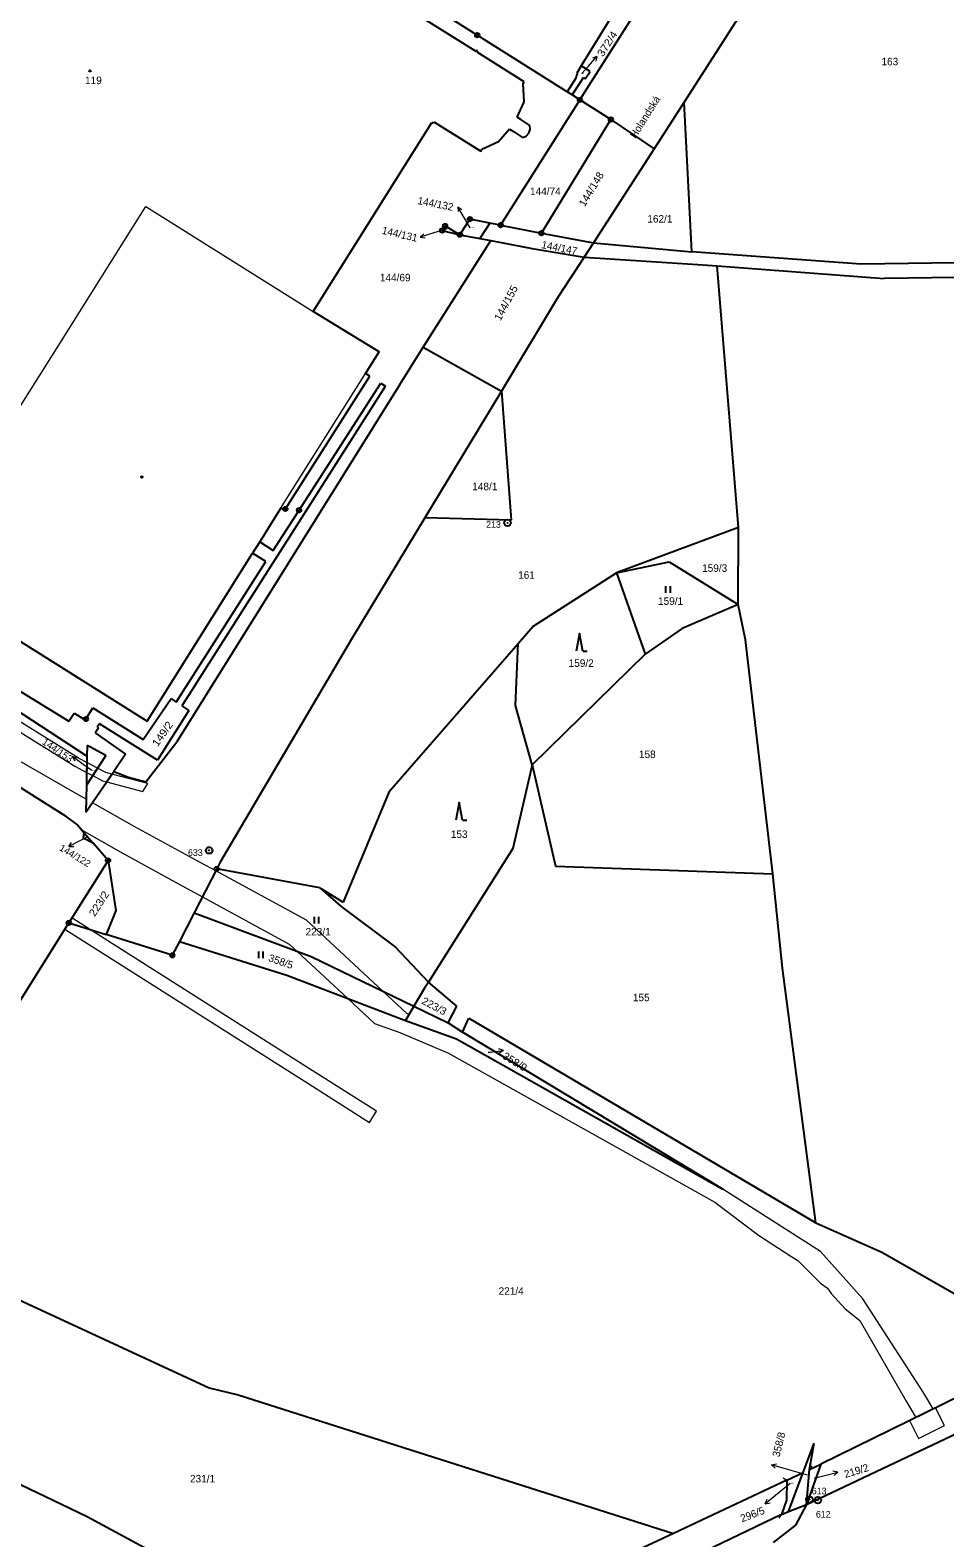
# Model space of a CAD drawing. Extents: x -645290 to -643454, y -1064771 to -1062356.
# Drawn here: x -644073.2 to -643865.7, y -1063369.7 to -1063027.7 of the extents above; entities that cross this region are included whole.
import ezdxf
from ezdxf.enums import TextEntityAlignment as Align

# ---------------------------------------------------------------- set-up
doc = ezdxf.new("R2010")
doc.units = 0
doc.header["$LTSCALE"] = 0.68
for name, color, linetype, lineweight in [('1', 7, 'Continuous', 25), ('13', 7, 'Continuous', 13), ('3', 7, 'Continuous', 25), ('4', 7, 'Continuous', 13), ('5', 7, 'Continuous', 25), ('7', 7, 'Continuous', 13), ('8', 7, 'Continuous', 25)]:
    doc.layers.add(name, color=color, linetype=linetype, lineweight=lineweight)
doc.layers.add('2', color=7, linetype='Continuous')

msp = doc.modelspace()

# ---------------------------------------------------------------- linework, layer by layer
at = {"layer": '1'}
for p, q in [((-643972.05, -1063032.56), (-644071.08, -1062970.39)), ((-643948.47, -1063043.52), (-643911.32, -1062984.88)), ((-643886.01, -1062983.52), (-643924.81, -1063044)), ((-643919.63, -1062989.21), (-643948.16, -1063035.76)), ((-643971.78, -1063028.84), (-644020.09, -1062998.39)), ((-643951.4, -1063041.68), (-643971.78, -1063028.84)), ((-643971.91, -1063032.34), (-643972.05, -1063032.56)), ((-643971.86, -1063032.26), (-643971.91, -1063032.34)), ((-643971.61, -1063032.42), (-643971.86, -1063032.26)), ((-643971.8, -1063032.72), (-643971.61, -1063032.42)), ((-643961.09, -1063039.44), (-643971.8, -1063032.72)), ((-643948.16, -1063035.76), (-643949.21, -1063037.48)), ((-643946.13, -1063037.05), (-643948.16, -1063035.76)), ((-643961.33, -1063039.82), (-643961.09, -1063039.44)), ((-643961.09, -1063043.97), (-643961.33, -1063039.82)), ((-643949.39, -1063038.58), (-643951.4, -1063041.68)), ((-643950.24, -1063042.41), (-643948.23, -1063039.28)), ((-643949.22, -1063037.96), (-643949.39, -1063038.58)), ((-643949.11, -1063037.54), (-643949.22, -1063037.96)), ((-643949.21, -1063037.48), (-643949.11, -1063037.54)), ((-643948.23, -1063039.28), (-643947.85, -1063038.67)), ((-643947.85, -1063038.67), (-643947.72, -1063038.46)), ((-643947.72, -1063038.46), (-643947.26, -1063038.77)), ((-643947.26, -1063038.77), (-643946.13, -1063037.05)), ((-643948.47, -1063043.52), (-643966.47, -1063071.93)), ((-643950.24, -1063042.41), (-643951.4, -1063041.68)), ((-643948.47, -1063043.52), (-643950.24, -1063042.41)), ((-643941.45, -1063047.96), (-643948.47, -1063043.52)), ((-643962.73, -1063047.41), (-643961.09, -1063043.97)), ((-643924.81, -1063044), (-643931.65, -1063054.65)), ((-643923.12, -1063077.97), (-643924.81, -1063044)), ((-644009.01, -1063091.53), (-643982.06, -1063048.68)), ((-643982.06, -1063048.68), (-643981.78, -1063048.77)), ((-643981.78, -1063048.77), (-643981.64, -1063048.5)), ((-643981.64, -1063048.5), (-643972.77, -1063054.04)), ((-643964.46, -1063050.17), (-643966.94, -1063053.05)), ((-643964.46, -1063050.17), (-643963.58, -1063050.72)), ((-643961.86, -1063047.99), (-643962.73, -1063047.41)), ((-643959.85, -1063049.36), (-643961.86, -1063047.99)), ((-643960.07, -1063051.08), (-643959.78, -1063050.25)), ((-643959.78, -1063050.25), (-643959.85, -1063049.36)), ((-643957.21, -1063073.75), (-643941.45, -1063047.96)), ((-643941.45, -1063047.96), (-643931.65, -1063054.65)), ((-643966.94, -1063053.05), (-643970.71, -1063054.8)), ((-643963.58, -1063050.72), (-643961.51, -1063052.03)), ((-643961.51, -1063052.03), (-643960.67, -1063051.72)), ((-643960.67, -1063051.72), (-643960.07, -1063051.08)), ((-643972.77, -1063054.04), (-643970.95, -1063055.18)), ((-643970.95, -1063055.18), (-643970.71, -1063054.8)), ((-643931.65, -1063054.65), (-643945.43, -1063075.94)), ((-643975.72, -1063074.1), (-643973.43, -1063070.56)), ((-643968.91, -1063071.45), (-643973.43, -1063070.56)), ((-643979.72, -1063073.14), (-643979.06, -1063072.12)), ((-643979.72, -1063073.14), (-643975.72, -1063074.1)), ((-643979.06, -1063072.12), (-643975.72, -1063074.1)), ((-643975.72, -1063074.1), (-643971.17, -1063074.97)), ((-643968.91, -1063071.45), (-643971.17, -1063074.97)), ((-643966.47, -1063071.93), (-643968.91, -1063071.45)), ((-643966.47, -1063071.93), (-643957.21, -1063073.75)), ((-643957.21, -1063073.75), (-643945.43, -1063075.94)), ((-643984.01, -1063099.62), (-643968.69, -1063075.44)), ((-643971.17, -1063074.97), (-643968.69, -1063075.44)), ((-643968.69, -1063075.44), (-643959.33, -1063077.22)), ((-643959.33, -1063077.22), (-643947.54, -1063079.19)), ((-643945.43, -1063075.94), (-643947.54, -1063079.19)), ((-643945.43, -1063075.94), (-643923.12, -1063077.97)), ((-643947.54, -1063079.19), (-643953.38, -1063088.21)), ((-643947.54, -1063079.19), (-643921.76, -1063080.86)), ((-643884.68, -1063080.78), (-643923.12, -1063077.97)), ((-643921.76, -1063080.86), (-643917.3, -1063081.19)), ((-643912.5, -1063140.52), (-643917.3, -1063081.19)), ((-643917.3, -1063081.19), (-643879.42, -1063084.02)), ((-643837.07, -1063080.08), (-643884.68, -1063080.78)), ((-643833.92, -1063083.46), (-643879.42, -1063084.02)), ((-643953.38, -1063088.21), (-643966.3, -1063109.61)), ((-643989.36, -1063108.06), (-643984.01, -1063099.62)), ((-643984.01, -1063099.62), (-643966.3, -1063109.61)), ((-643989.36, -1063108.06), (-644039.93, -1063189.16)), ((-644015.31, -1063136.3), (-643996.12, -1063106.19)), ((-644012.2, -1063136.58), (-643993.65, -1063107.74)), ((-644010.59, -1063136.73), (-643992.55, -1063108.43)), ((-643996.12, -1063106.19), (-643997.14, -1063105.55)), ((-643993.65, -1063107.74), (-643992.55, -1063108.43)), ((-643966.3, -1063109.61), (-643983.63, -1063138.3)), ((-643966.3, -1063109.61), (-643964.11, -1063138.86)), ((-644035.79, -1063176.25), (-644010.59, -1063136.73)), ((-644016.38, -1063136.2), (-644021.12, -1063143.76)), ((-644018.07, -1063145.71), (-644012.2, -1063136.58)), ((-644015.31, -1063136.3), (-644016.38, -1063136.2)), ((-643983.63, -1063138.3), (-644000.27, -1063165.84)), ((-643964.11, -1063138.86), (-643983.63, -1063138.3)), ((-643912.5, -1063140.52), (-643940.21, -1063150.77)), ((-643912.54, -1063157.95), (-643912.5, -1063140.52)), ((-644021.12, -1063143.76), (-644022.73, -1063146.32)), ((-644021.12, -1063143.76), (-644018.07, -1063145.71)), ((-644046.66, -1063184.45), (-644022.73, -1063146.32)), ((-644040.05, -1063180.11), (-644019.72, -1063148.25)), ((-644019.72, -1063148.25), (-644022.73, -1063146.32)), ((-643940.21, -1063150.77), (-643928.21, -1063148.29)), ((-643928.21, -1063148.29), (-643912.54, -1063157.95)), ((-644100.11, -1063150.87), (-644046.66, -1063184.45)), ((-643959.16, -1063163.01), (-643940.21, -1063150.77)), ((-643940.21, -1063150.77), (-643933.67, -1063169.22)), ((-644060.32, -1063192.37), (-644113.26, -1063157.87)), ((-644105.82, -1063159.04), (-644064.47, -1063184.41)), ((-643912.54, -1063157.95), (-643925.3, -1063163.46)), ((-643910.9, -1063165.99), (-643912.54, -1063157.95)), ((-643962.49, -1063166.82), (-643959.16, -1063163.01)), ((-644000.27, -1063165.84), (-644030.1, -1063216.46)), ((-643925.3, -1063163.46), (-643933.67, -1063169.22)), ((-643904.73, -1063219.08), (-643910.9, -1063165.99)), ((-643991.77, -1063200.37), (-643962.49, -1063166.82)), ((-643963.07, -1063180.87), (-643962.49, -1063166.82)), ((-643933.67, -1063169.22), (-643959.3, -1063194.35)), ((-644120.82, -1063170.91), (-644065.09, -1063205.97)), ((-644035.79, -1063176.25), (-644038.78, -1063180.95)), ((-644047.54, -1063188.64), (-644041.24, -1063179.32)), ((-644041.24, -1063179.32), (-644040.05, -1063180.11)), ((-644064.47, -1063184.41), (-644063.23, -1063182.62)), ((-644063.23, -1063182.62), (-644060.69, -1063184.18)), ((-644060.56, -1063183.97), (-644058.98, -1063181.46)), ((-644058.98, -1063181.46), (-644047.54, -1063188.64)), ((-644037.2, -1063182), (-644044.35, -1063193.29)), ((-644038.78, -1063180.95), (-644037.2, -1063182)), ((-643959.3, -1063194.35), (-643963.07, -1063180.87)), ((-644060.69, -1063184.18), (-644060.56, -1063183.97)), ((-644057.71, -1063186.02), (-644058.43, -1063187.12)), ((-644058.43, -1063187.12), (-644051.58, -1063191.93)), ((-644057.51, -1063185.02), (-644058.02, -1063185.83)), ((-644058.02, -1063185.83), (-644057.71, -1063186.02)), ((-644044.35, -1063193.29), (-644057.51, -1063185.02)), ((-644060.28, -1063189.93), (-644060.32, -1063192.37)), ((-644059.49, -1063190.36), (-644060.28, -1063189.93)), ((-644058.04, -1063191.16), (-644059.49, -1063190.36)), ((-644046.99, -1063198.23), (-644039.93, -1063189.16)), ((-644056.03, -1063192.27), (-644060.44, -1063198.94)), ((-644060.32, -1063192.37), (-644060.44, -1063198.94)), ((-644056.03, -1063192.27), (-644058.04, -1063191.16)), ((-644051.58, -1063191.93), (-644054.25, -1063195.85)), ((-644060.55, -1063205.1), (-644054.25, -1063195.85)), ((-644054.25, -1063195.85), (-644050.87, -1063197.15)), ((-644050.87, -1063197.15), (-644046.99, -1063198.23)), ((-643959.3, -1063194.35), (-643963.72, -1063213.32)), ((-643959.3, -1063194.35), (-643954.05, -1063217.36)), ((-644060.44, -1063198.94), (-644060.55, -1063205.1)), ((-643991.77, -1063200.37), (-644002.22, -1063225.49)), ((-644062.5, -1063207.96), (-644065.09, -1063205.97)), ((-644062.5, -1063207.96), (-644061.02, -1063209.68)), ((-644061.02, -1063209.68), (-644061.15, -1063211.01)), ((-644058.9, -1063212.14), (-644061.15, -1063211.01)), ((-644061.02, -1063209.68), (-644058.9, -1063212.14)), ((-644055.54, -1063216.03), (-644058.9, -1063212.14)), ((-643963.72, -1063213.32), (-643982.84, -1063243.64)), ((-644055.54, -1063216.03), (-644064.43, -1063230.22)), ((-644055.54, -1063216.03), (-644055.3, -1063217.57)), ((-644055.3, -1063217.57), (-644053.77, -1063227.42)), ((-644030.87, -1063217.96), (-644036.02, -1063227.96)), ((-644030.1, -1063216.46), (-644030.87, -1063217.96)), ((-644007.47, -1063222.27), (-644030.87, -1063217.96)), ((-643954.05, -1063217.36), (-643904.73, -1063219.08)), ((-643902.48, -1063240.48), (-643904.73, -1063219.08)), ((-644007.47, -1063222.27), (-644002.22, -1063225.49)), ((-644007.47, -1063222.27), (-644002.63, -1063226.47)), ((-644053.77, -1063227.42), (-644056, -1063232.86)), ((-644036.02, -1063227.96), (-644039.36, -1063234.45)), ((-644036.02, -1063227.96), (-644009.43, -1063237.85)), ((-644002.63, -1063226.47), (-643990.35, -1063235.73)), ((-644108.45, -1063300.52), (-644064.43, -1063230.22)), ((-644064.43, -1063230.22), (-644056, -1063232.86)), ((-644040.97, -1063237.56), (-644056, -1063232.86)), ((-644039.36, -1063234.45), (-644040.97, -1063237.56)), ((-644039.36, -1063234.45), (-644014.97, -1063242.04)), ((-644009.43, -1063237.85), (-643986.15, -1063249.13)), ((-643982.84, -1063243.64), (-643990.35, -1063235.73)), ((-643894.95, -1063298.27), (-643902.48, -1063240.48)), ((-644014.97, -1063242.04), (-643988.07, -1063252.36)), ((-643983.72, -1063245.03), (-643986.15, -1063249.13)), ((-643982.84, -1063243.64), (-643983.72, -1063245.03)), ((-643976.39, -1063249.11), (-643982.84, -1063243.64)), ((-643986.15, -1063249.13), (-643988.07, -1063252.36)), ((-643986.15, -1063249.13), (-643978.34, -1063252.91)), ((-643978.34, -1063252.91), (-643976.39, -1063249.11)), ((-643975.08, -1063255.03), (-643973.71, -1063251.82)), ((-643973.71, -1063251.82), (-643894.95, -1063298.27)), ((-643988.07, -1063252.36), (-643976.48, -1063256.51)), ((-643978.34, -1063252.91), (-643975.08, -1063255.03)), ((-643916.03, -1063290.57), (-643975.08, -1063255.03)), ((-643976.48, -1063256.51), (-643916.03, -1063290.57)), ((-643894.95, -1063298.27), (-643880.01, -1063304.89)), ((-644108.45, -1063300.52), (-644032.62, -1063335.66)), ((-643880.01, -1063304.89), (-643861.29, -1063315.59)), ((-644128.32, -1063332.26), (-644060.42, -1063364.75)), ((-644032.62, -1063335.66), (-644026.05, -1063337.25)), ((-644026.05, -1063337.25), (-643927.27, -1063368.68)), ((-643857.36, -1063335.06), (-643893.79, -1063352.95)), ((-643897.06, -1063362.17), (-643858.41, -1063343.81)), ((-643897.81, -1063354.89), (-643895.32, -1063348.19)), ((-643896.36, -1063354.21), (-643895.32, -1063348.19)), ((-643893.79, -1063352.95), (-643897.06, -1063362.17)), ((-643897.06, -1063362.17), (-643896.36, -1063354.21)), ((-643896.36, -1063354.21), (-643893.79, -1063352.95)), ((-643901.5, -1063356.61), (-643927.27, -1063368.68)), ((-643901.5, -1063356.61), (-643901.57, -1063361.14)), ((-643901.5, -1063356.61), (-643897.81, -1063354.89)), ((-643901.12, -1063363.76), (-643897.81, -1063354.89)), ((-643901.57, -1063361.14), (-643902.76, -1063364.4)), ((-644060.42, -1063364.75), (-644036.09, -1063377.9)), ((-643902.76, -1063364.4), (-643990.03, -1063406.29)), ((-643902.76, -1063364.4), (-643901.12, -1063363.76)), ((-643901.12, -1063363.76), (-643897.06, -1063362.17)), ((-643897.06, -1063362.17), (-643899.58, -1063366.85)), ((-643899.58, -1063366.85), (-643904.6, -1063370.72)), ((-643927.27, -1063368.68), (-643987.39, -1063396.85))]:
    msp.add_line(p, q, dxfattribs=at)
msp.add_lwpolyline([(-643997.14, -1063105.55), (-643994.05, -1063100.64), (-644009.01, -1063091.53)], dxfattribs=at)
at = {"layer": '13'}
for points in [[(-644175.47, -1063119.76), (-644177.34, -1063118.44), (-644175.73, -1063115.62), (-644177.14, -1063114.69), (-644177.4, -1063114.52), (-644180.02, -1063119.08), (-644176.52, -1063121.53), (-644166.59, -1063128.45), (-644146.52, -1063141.67), (-644115.44, -1063161.49), (-644083.43, -1063182.03), (-644063.09, -1063194.64), (-644060.39, -1063196.06), (-644060.35, -1063193.82), (-644062.09, -1063192.9), (-644082.37, -1063180.33), (-644114.36, -1063159.81), (-644145.44, -1063139.99), (-644165.45, -1063126.81)], [(-644059.01, -1063196.79), (-644056.77, -1063197.98), (-644055.86, -1063198.22), (-644054.66, -1063196.45), (-644056.07, -1063196.08), (-644057.91, -1063195.11), (-644060.35, -1063193.82), (-644060.39, -1063196.06)], [(-644055.86, -1063198.22), (-644047.65, -1063200.37), (-644046.53, -1063198.6), (-644054.66, -1063196.45)], [(-643996.24, -1063275.47), (-643994.63, -1063272.94), (-644010.67, -1063262.76), (-644059.48, -1063231.77), (-644063.72, -1063229.08), (-644064.43, -1063230.22), (-644065.31, -1063231.62), (-644010.85, -1063266.19)], [(-643873.7, -1063343.09), (-643871.64, -1063347.17), (-643865.75, -1063344.2), (-643867.78, -1063340.18), (-643868.35, -1063340.46), (-643872.3, -1063342.4)]]:
    msp.add_lwpolyline(points, close=True, dxfattribs=at)
msp.add_lwpolyline([(-644122.95, -1063169.57), (-644065.09, -1063205.97), (-644062.5, -1063207.96), (-644061.44, -1063209.19), (-644052.63, -1063214.2), (-644037.87, -1063222.23), (-644034.12, -1063224.28), (-644014.42, -1063235), (-644012.64, -1063236.66), (-644001.13, -1063247.35), (-643995.05, -1063253), (-643989.34, -1063255.07), (-643978.33, -1063259.78), (-643917.88, -1063293.56), (-643907.95, -1063301.06), (-643900.38, -1063305.92), (-643899.07, -1063306.76), (-643893.86, -1063311.96), (-643892.33, -1063313.08), (-643891.51, -1063314.3), (-643888.31, -1063317.73), (-643885, -1063320.4), (-643874.48, -1063338.71), (-643872.3, -1063342.4), (-643868.35, -1063340.46), (-643870.46, -1063336.88), (-643884.32, -1063315.48), (-643893.91, -1063304.78), (-643916.03, -1063290.57), (-643972.35, -1063258.84), (-643977.45, -1063256.16), (-643988.07, -1063252.36), (-643987.27, -1063251.01), (-643987.76, -1063250.76), (-643993.18, -1063245.72), (-644010.54, -1063229.6), (-644031.1, -1063218.41), (-644034.49, -1063216.56), (-644049.46, -1063208.42), (-644059.08, -1063202.94), (-644060.55, -1063205.1), (-644060.5, -1063202.14), (-644061.99, -1063201.29), (-644081.47, -1063190.21)], dxfattribs=at)
at = {"layer": '3'}
for p, q in [((-643928.951, -1063155.32), (-643928.951, -1063153.82)), ((-643927.95, -1063155.32), (-643927.95, -1063153.82)), ((-643947.85, -1063168.56), (-643946.854, -1063168.56)), ((-643975.1, -1063206.88), (-643974.104, -1063206.88)), ((-644008.681, -1063230.35), (-644008.681, -1063228.85)), ((-644007.68, -1063230.35), (-644007.68, -1063228.85)), ((-644021.351, -1063238.23), (-644021.351, -1063236.73)), ((-644020.35, -1063238.23), (-644020.35, -1063236.73))]:
    msp.add_line(p, q, dxfattribs=at)
for points in [[(-643947.85, -1063168.56), (-643948.6, -1063164.56), (-643949.35, -1063168.56)], [(-643975.1, -1063206.88), (-643975.85, -1063202.88), (-643976.6, -1063206.88)]]:
    msp.add_lwpolyline(points, dxfattribs=at)
at = {"layer": '4'}
for p, q in [((-644049.92, -1063072.37), (-644046.97, -1063067.67)), ((-644046.97, -1063067.67), (-644009.01, -1063091.53)), ((-644066.89, -1063099.35), (-644049.92, -1063072.37)), ((-644089.68, -1063135.58), (-644066.89, -1063099.35)), ((-644016.38, -1063136.2), (-643997.14, -1063105.55)), ((-643895.829, -1063353.362), (-643896.359, -1063354.21)), ((-643902.375, -1063356.124), (-643901.5, -1063356.609)), ((-643903.261, -1063365.266), (-643902.761, -1063364.4))]:
    msp.add_line(p, q, dxfattribs=at)
at = {"layer": '5'}
for centre in [(-644059.6368, -1063036.9392), (-644047.8668, -1063129.0692)]:
    msp.add_circle(centre, 0.175, dxfattribs=at)
at = {"layer": '7'}
for p, q in [((-643944.621, -1063033.645), (-643945.656, -1063034.072)), ((-643976.18, -1063067.741), (-643976.113, -1063068.859)), ((-643984.71, -1063074.657), (-643983.606, -1063074.843)), ((-644063.618, -1063192.486), (-644063.102, -1063193.48)), ((-644064.45, -1063212.889), (-644063.33, -1063212.861)), ((-643965.841, -1063259.134), (-643966.896, -1063258.759)), ((-643905.005, -1063353.133), (-643904.18, -1063353.89)), ((-643889.981, -1063354.783), (-643891.078, -1063354.559)), ((-643906.432, -1063361.979), (-643905.339, -1063361.737))]:
    msp.add_line(p, q, dxfattribs=at)
for points in [[(-643948.03, -1063037.56), (-643946.59, -1063035.91), (-643944.621, -1063033.645), (-643944.9, -1063034.729)], [(-643973.4, -1063072.51), (-643974.68, -1063070.34), (-643976.18, -1063067.741), (-643975.246, -1063068.358)], [(-643978.69, -1063072.8), (-643981.84, -1063073.78), (-643984.71, -1063074.657), (-643983.899, -1063073.886)], [(-644059.23, -1063195.65), (-644061.19, -1063194.25), (-644063.618, -1063192.486), (-644062.513, -1063192.67)], [(-644060.52, -1063210.81), (-644061.8, -1063211.48), (-644064.45, -1063212.889), (-644063.801, -1063211.977)], [(-643969.32, -1063259.56), (-643968.82, -1063259.5), (-643965.841, -1063259.134), (-643966.774, -1063259.753)], [(-643896.85, -1063355.5), (-643902.12, -1063353.96), (-643905.005, -1063353.133), (-643903.904, -1063352.928)], [(-643895.36, -1063356.2), (-643892.88, -1063355.56), (-643889.981, -1063354.783), (-643890.819, -1063355.526)], [(-643900.75, -1063357.36), (-643904.1, -1063360.09), (-643906.432, -1063361.979), (-643905.969, -1063360.959)]]:
    msp.add_lwpolyline(points, dxfattribs=at)
at = {"layer": '8'}
for centre, radius in [((-643971.78, -1063028.8399), 0.5), ((-643971.78, -1063028.8399), 0.0303), ((-643948.47, -1063043.5199), 0.5), ((-643948.47, -1063043.5199), 0.0303), ((-643941.45, -1063047.9599), 0.5), ((-643941.45, -1063047.9599), 0.0303), ((-643973.43, -1063070.5599), 0.5), ((-643973.43, -1063070.5599), 0.0303), ((-643979.72, -1063073.1399), 0.5), ((-643979.72, -1063073.1399), 0.0303), ((-643979.06, -1063072.1199), 0.5), ((-643979.06, -1063072.1199), 0.0303), ((-643975.72, -1063074.0999), 0.5), ((-643975.72, -1063074.0999), 0.0303), ((-643966.47, -1063071.9299), 0.5), ((-643966.47, -1063071.9299), 0.0303), ((-643957.21, -1063073.7499), 0.5), ((-643957.21, -1063073.7499), 0.0303), ((-644015.31, -1063136.2999), 0.5), ((-644015.31, -1063136.2999), 0.0303), ((-644012.2, -1063136.5799), 0.5), ((-644012.2, -1063136.5799), 0.0303), ((-643964.91, -1063139.4698), 0.75), ((-643964.91, -1063139.4698), 0.03), ((-644060.56, -1063183.9699), 0.5), ((-644060.56, -1063183.9699), 0.0303), ((-644032.62, -1063213.7498), 0.75), ((-644032.62, -1063213.7498), 0.03), ((-644055.54, -1063216.0299), 0.5), ((-644055.54, -1063216.0299), 0.0303), ((-644030.87, -1063217.9599), 0.5), ((-644030.87, -1063217.9599), 0.0303), ((-644064.43, -1063230.2199), 0.5), ((-644064.43, -1063230.2199), 0.0303), ((-644040.97, -1063237.5599), 0.5), ((-644040.97, -1063237.5599), 0.0303), ((-643896.42, -1063360.9798), 0.75), ((-643896.42, -1063360.9798), 0.03), ((-643894.49, -1063361.1398), 0.75), ((-643894.49, -1063361.1398), 0.03)]:
    msp.add_circle(centre, radius, dxfattribs=at)

# ---------------------------------------------------------------- texts
at = {"layer": '2'}
for s, height, rotation, width, p in [('372/4', 1.7, 57, 1.1, (-643943.263, -1063033.881)), ('144/148', 1.7, 59, 1.05, (-643947.385, -1063067.908)), ('144/155', 1.7, 62, 1.05, (-643966.514, -1063093.789)), ('149/2', 1.7, 55, 1.1, (-644044.281, -1063190.363)), ('223/3', 1.7, 332, 1.05, (-643984.559, -1063248.435)), ('358/9', 0.2, 333, 1.05, (-643969.342, -1063259.604)), ('358/9', 1.7, 328, 1.05, (-643966.209, -1063260.835))]:
    msp.add_text(s, height=height, rotation=rotation, dxfattribs=dict(at, width=width)).set_placement(p)
for s, height, p in [('163', 1.7, (-643880.06, -1063035.675)), ('119', 1.7, (-644060.75, -1063039.945)), ('162/1', 1.7, (-643933.18, -1063071.354)), ('144/131', 0.2, (-643978.69, -1063072.85)), ('144/132', 0.2, (-643973.4, -1063072.56)), ('148/1', 1.7, (-643972.9, -1063132.064)), ('159/3', 1.7, (-643920.75, -1063150.574)), ('161', 1.7, (-643962.49, -1063152.145)), ('159/1', 1.7, (-643930.75, -1063158.064)), ('159/2', 1.7, (-643951.03, -1063172.125)), ('158', 1.7, (-643935.09, -1063192.814)), ('144/153', 0.2, (-644059.23, -1063195.699)), ('155', 1.7, (-643936.46, -1063247.975)), ('221/4', 1.7, (-643966.92, -1063314.564)), ('231/1', 1.7, (-644036.94, -1063357.125)), ('296/5', 0.2, (-643900.75, -1063357.41)), ('358/8', 0.2, (-643896.85, -1063355.55)), ('219/2', 0.2, (-643895.36, -1063356.25))]:
    msp.add_text(s, height=height, dxfattribs=at).set_placement(p)
for s, height, p in [('372/4', 0.2, (-643948.029, -1063037.61)), ('144/74', 1.7, (-643956.31, -1063065.094)), ('144/69', 1.7, (-643990.38, -1063084.675)), ('144/122', 0.2, (-644060.519, -1063210.86)), ('153', 1.7, (-643975.869, -1063210.935)), ('223/1', 1.7, (-644007.87, -1063233.064))]:
    msp.add_text(s, height=height, dxfattribs=at).set_placement(p, align=Align.CENTER)
for s, rotation, p in [('144/132', 349, (-643977.3554, -1063068.6984)), ('144/131', 347, (-643985.5304, -1063075.7282)), ('358/8', 76, (-643901.8344, -1063345.9723)), ('296/5', 21, (-643906.3712, -1063364.1555))]:
    msp.add_text(s, height=1.7, rotation=rotation, dxfattribs=at).set_placement(p, align=Align.RIGHT)
for s, rotation, p in [('144/147', 349, (-643957.321, -1063077.127)), ('358/5', 341, (-644019.278, -1063238.841)), ('219/2', 17, (-643888.229, -1063356.143))]:
    msp.add_text(s, height=1.7, rotation=rotation, dxfattribs=at).set_placement(p)
at = {"layer": '2', "width": 1.05}
for s, rotation, p in [('144/153', 326, (-644064.1864, -1063193.873)), ('144/122', 329, (-644060.0856, -1063217.6199))]:
    msp.add_text(s, height=1.535, rotation=rotation, dxfattribs=at).set_placement(p, align=Align.RIGHT)
at = {"layer": '2', "width": 1.1}
msp.add_text('223/2', height=1.7, rotation=57, dxfattribs=at).set_placement((-644056.8804, -1063226.3059), align=Align.CENTER)
at = {"layer": '7'}
msp.add_text('Holandská', height=1.7, rotation=58, dxfattribs=at).set_placement((-643932.9883, -1063047.8494), align=Align.CENTER)
at = {"layer": '8'}
for s, p in [('213', (-643966.409, -1063140.587)), ('613', (-643892.529, -1063359.837)), ('612', (-643891.589, -1063365.097))]:
    msp.add_text(s, height=1.5, dxfattribs=at).set_placement(p, align=Align.RIGHT)
msp.add_text('633', height=1.5, dxfattribs=at).set_placement((-644037.4, -1063215.004))

doc.saveas('drawing.dxf')
